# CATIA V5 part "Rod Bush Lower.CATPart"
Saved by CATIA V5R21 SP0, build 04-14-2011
Part number: Rod Nush Lower
Bounding box of the stored display mesh (mm): x -7.5 to 7.5, y -7.312 to 7.312, z -12 to 12
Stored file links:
  D:\CATIA V5R21 E-RESOURCES\CATIA-V5R21\catia-v5r21-Prts\c13_catia_v5r21_prt\c13_catia_v5r21_figr_13-41\Part & Asm files\Rod Bush Lower.CATPart
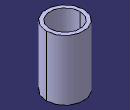
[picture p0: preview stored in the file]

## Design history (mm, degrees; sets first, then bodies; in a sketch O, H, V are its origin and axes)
Body1 (main body)
  Sketch1 on xy-plane, origin (0, 0, 0), H (1, 0, 0), V (0, 1, 0)
    circle A1 centre (0, 0) radius 6
    circle A2 centre (0, 0) radius 7.5
    point P1 (0, 0)
    radius A2 = 7.5
    radius A1 = 6
    coincidence: P1 H
    concentricity: A1 A2
  Pad1: profile Sketch1, direction (0, 0, 1), length 12, mirrored extent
